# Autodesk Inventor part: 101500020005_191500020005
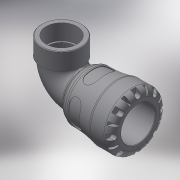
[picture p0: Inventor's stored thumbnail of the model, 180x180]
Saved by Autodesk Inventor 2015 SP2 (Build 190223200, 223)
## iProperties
Created: 2016-12
Part Number: 101500020005_191500020005
Material: Generic
Description: PLASSON 90° ELBOW WITH THREADED FEMALE OFFTAKE 20X1/2" SERIES 1
Document SubType Name: Modeling
Designer: KIM
Mass: 557.611 g
Surface Area: 990.043 cm^2
Volume: 557.611 cm^3
Density: 1 g/cm^3
Appearance: Default
Author: KIM
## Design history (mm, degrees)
derived "1015.ipt"
feature "Solid1::1015.ipt"
tag "TaggingFeature1"
body "Solid1"
other parameters: "d1" = 18.9, "d3" = 25, "d4" = 41, "d8" = 36.08, "d13" = 6.4, "d14" = 6.4, "d15" = 0, "d17" = 360 deg, "d19" = 8 deg, "d20" = 0.4, "d21" = 0.4, "d22" = 8 deg, "d24" = 0, "d26" = 360 deg, "d33" = 4.1, "d43" = 33.62, "d51" = 0.41, "d54" = 7, "d55" = 4.4, "d57" = 12.544, "d58" = 0, "d74" = 0, "d78" = 45, "d82" = 0.4, "d115" = 360 deg, "d207" = 90 deg, "d228" = 5.95, "d247" = 0.82, "d248" = 2.7, "d268" = 19.844, "d269" = 2.7, "d270" = 67, "d279" = 39, "d281" = 2.79465, "d294" = 18.631, "d295" = 17, "d296" = 18.7, "d297" = 16.7679, "d299" = 21.79827, "d300" = 16.7679, "d301" = 0, "d302" = 0, "d303" = 5.91086, "d306" = 0, "d307" = 9, "d308" = 8, "d310" = 3, "E_" = 41, "l_" = 45, "A_" = 67, "A_1" = 39, "l_2" = 17, "Rp_" = 18.631, "d9" = 8, "d11" = 41, "d12" = 25, "d298" = 24.2203
